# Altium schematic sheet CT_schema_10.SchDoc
size 281 x 153 mm
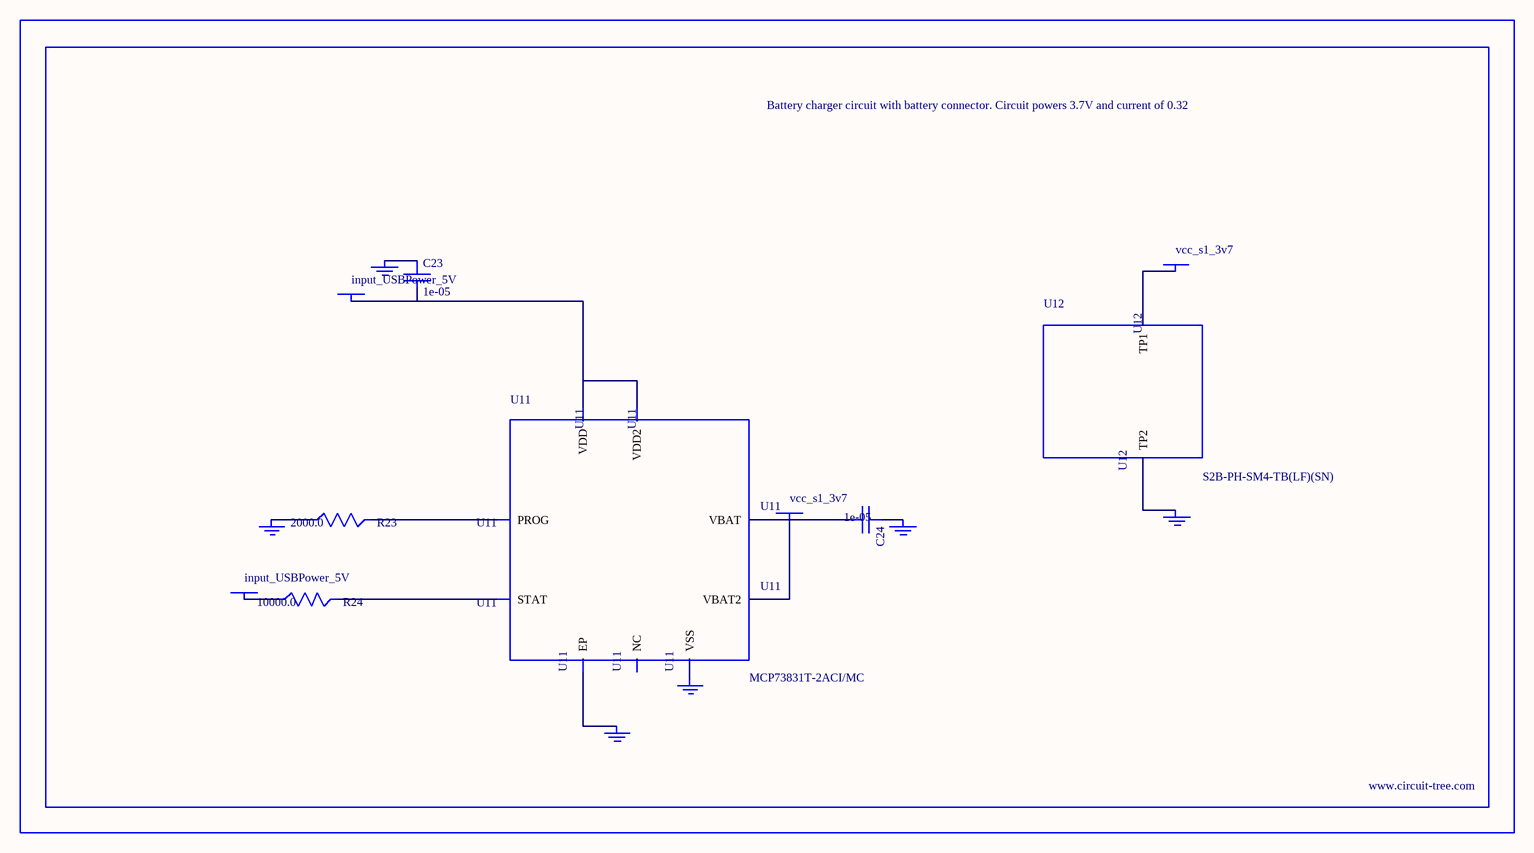
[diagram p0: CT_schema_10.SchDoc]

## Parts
BORDER9  (no value)
C23  1e-05  [C1206]
C24  1e-05  [C1206]
GND_INSTANCE_9_0  (no value)
GND_INSTANCE_9_1  (no value)
GND_INSTANCE_9_2  (no value)
GND_INSTANCE_9_3  (no value)
GND_INSTANCE_9_4  (no value)
GND_INSTANCE_9_5  (no value)
POWER_INSTANCE_9_0  input_USBPower_5V
POWER_INSTANCE_9_1  input_USBPower_5V
POWER_INSTANCE_9_2  vcc_s1_3v7
POWER_INSTANCE_9_3  vcc_s1_3v7
R23  2000.0  [R0603]
R24  10000.0  [R0603]
U11  MCP73831T-2ACI/MC  [DFN8_2X3MC]
U12  S2B-PH-SM4-TB(LF)(SN)  [JST-2-SMD]

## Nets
NetC23_1: C23.1 GND_INSTANCE_9_0.0(GND)
NetC23_2: C23.2 POWER_INSTANCE_9_0.0(PWR) U11.1(VDD) U11.2(VDD2)
NetC24_1: C24.1 GND_INSTANCE_9_1.0(GND)
NetC24_2: C24.2 POWER_INSTANCE_9_2.0(PWR) U11.3(VBAT) U11.4(VBAT2)
NetGND_INSTANCE_9_2_0: GND_INSTANCE_9_2.0(GND) R23.1
NetGND_INSTANCE_9_3_0: GND_INSTANCE_9_3.0(GND) U11.9(EP)
NetGND_INSTANCE_9_4_0: GND_INSTANCE_9_4.0(GND) U11.6(VSS)
NetGND_INSTANCE_9_5_0: GND_INSTANCE_9_5.0(GND) U12.2(TP2)
NetPOWER_INSTANCE_9_1_0: POWER_INSTANCE_9_1.0(PWR) R24.1
NetPOWER_INSTANCE_9_3_0: POWER_INSTANCE_9_3.0(PWR) U12.1(TP1)
NetR23_2: R23.2 U11.8(PROG)
NetR24_2: R24.2 U11.5(STAT)

Not connected (* = marked no-connect by the designer): U11 7(NC)

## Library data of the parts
BORDER9 = BORDER_PAGE9
C23 C24 = C1206C106K3RACTU
GND_INSTANCE_9_0-GND_INSTANCE_9_5 = GND
POWER_INSTANCE_9_0-POWER_INSTANCE_9_3 = PWR
R23 = RC0603JR-072KL
R24 = RC0603JR-0710KL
